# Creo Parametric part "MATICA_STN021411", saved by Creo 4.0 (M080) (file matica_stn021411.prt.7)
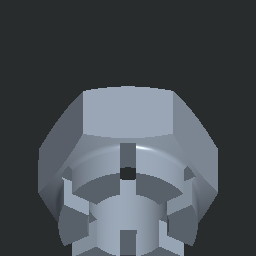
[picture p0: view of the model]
Units: millimeter Kilogram Sec (mmKs); MM, KILOGRAM, SECS
Materials in the file: OCEL_N

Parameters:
  MFG_WP_MATERIAL = "OCEL"
  NAZOV = "MATICA_STN021411"
  NORMA = "STN 02 1411"
  PTC_MATERIAL_NAME = "OCEL_N"

Other parameters: P, HMOTNOST, HUSTOTA, D66, D32, D64, D33, D62

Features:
  1. datum plane "DTM1"
  2. cut
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
Other named items: THRU

Layers: 1, 2, 3, 4, 5, 6, 7, 8, 9, 10, 11, 12, 13, 14, 15, 16, 17, 18, 19, 20, 21, 22, 23, 24, 25, 26, 27, 28, 29, 30, 31, 32

Family table entries: GENERIC, MATICA_M4, MATICA_STN021411, value(d_val), value(i_val), !/1, !/N, 2/N, MATICA_M5, MATICA_STN021411, 2/ , !/1, !/N, 2/N, MATICA_M6, MATICA_STN021411, 2/$, !/1, !/N, 2/N, MATICA_M8, MATICA_STN021411, !/ , 2/#, 2/*, !/1, !/N, 2/N, MATICA_M8X1, MATICA_STN021411, !/ , 2/#, 2/*, !/1, !/N, 2/N, MATICA_M10, MATICA_STN021411, !/$, 2/(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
